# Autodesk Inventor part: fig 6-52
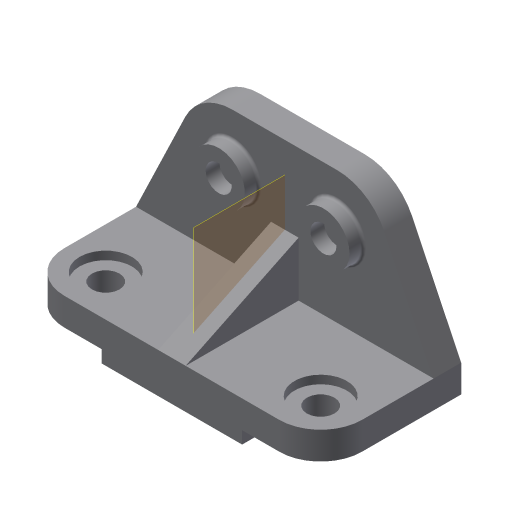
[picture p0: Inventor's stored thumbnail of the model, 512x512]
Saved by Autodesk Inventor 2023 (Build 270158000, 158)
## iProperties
Created: 2001-12
Part Number: fig 6-52
Document SubType Name: Modeling
Designer: Renu Muthoo
Density: 1 g/cm^3
Material: Generic
Appearance: Default
Control State: 0
Master: False
Checked Out: False
Shininess: 77.0
Length Units: 11269
Angle Units: 11279
Time Units: 11290
Mass Units: 11283
Length Display Precision: 3
Angle Display Precision: 2
Density: 0.0
Volumn: 0.0
Area: 0.0
PropertySet Name: Model Information
Author: Renu Muthoo
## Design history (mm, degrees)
node "Sketch1"
sketch "Sketch2"
  geometry: L1 (-67.219, 19.116)-(148.781, 19.116); L2 (148.781, 19.116)-(148.781, -0.884); L3 (-67.219, -0.884)-(-67.219, 19.116); L4 (-10.219, -0.884)-(-10.219, -9.884); L5 (-10.219, -9.884)-(91.781, -9.884); L6 (91.781, -9.884)-(91.781, -0.884); L7 (148.781, -0.884)-(91.781, -0.884); L8 (-10.219, -0.884)-(-67.219, -0.884)
  constraints: 16 end point, 5 parallel, 4 perpendicular, 2 equal length, 1 horizontal
  dimensions: "d0" = 102 distance of L4.end L5.end; "d1" = 57 distance of L4.start L3.start; "d2" = 29 distance between parallel lines of L1 L5; "d3" = 20 distance of L1.end L2.end
extrude "Extrusion1" new body sketch "Sketch2" distance "d4" = 102; taper "d5" = 0 deg
sketch "Sketch3"
  geometry: L1 (67.219, -19.116)-(-148.781, -19.116) reference; L2 (67.219, -19.116)-(31.475, -93.564); L3 (-2.781, -115.116)-(-78.781, -115.116); L4 (-113.038, -93.564)-(-148.781, -19.116); A1 r 38 centre (-2.781, -77.116) between (-2.781, -115.116) and (31.475, -93.564); A2 r 38 centre (-78.781, -77.116) between (-113.038, -93.564) and (-78.781, -115.116)
  constraints: 6 end point, 4 point on circle, 4 tangent, 2 centre point, 1 equal length, 1 equal radius, 1 parallel
  dimensions: "d6" = 96 distance between parallel lines of L3 L1; "d7" = 38 radius of A1; "d8" = 76 distance of A2.centre A1.centre
extrude "Extrusion2" join sketch "Sketch3" distance "d9" = 20; taper "d10" = 0 deg
fillet "Fillet1" dims "d11" = 30
workplane "Work Plane1"
sketch "Sketch5"
  geometry: A1 r 30 centre (-30, 0) between (-30, -30) and (0, 0) reference; 1 further point
  constraints: 1 coincident
hole "Hole1" sketch "Sketch5" at (-30, 0) diameter "d16" = 20; stored, may be unused: countersink angle "d20" = 82 deg, drill point angle "d22" = 118 deg; dims "d17" = 6, "d18" = 38, "d19" = 6, "d21" = 8
sketch "Sketch6"
  geometry: C1 r 19 at (-2.781, 77.116); C2 r 9.5 at (-2.781, 77.116); A1 r 38 centre (-2.781, 77.116) between (31.475, 93.564) and (-2.781, 115.116) reference
  constraints: 2 centre point, 2 coincident
  dimensions: "d23" = 38 diameter of C1; "d24" = 19 diameter of C2
extrude "Extrusion3" join sketch "Sketch6" distance "d25" = 10; taper "d26" = 0 deg
sketch "Sketch7"
  geometry: L1 (0, -82)-(-39.557, 0); L2 (0, -82)-(20, -82) reference; L3 (29, 22.405)-(29, -82); L4 (29, -82)-(0, -82); L5 (0, -82)-(0, 0); L6 (0, 0)-(-90.034, 0); L7 (-90.034, 0)-(-90.034, 22.405); L8 (-90.034, 22.405)-(29, 22.405); L9 (0, 0)-(-74.447, 0) reference
  constraints: 14 end point, 1 collinear, 1 point on line
feature "Rib3" sketch "Sketch7" dims "d35" = 10, "d36" = 20
fillet "Fillet3" dims "d37" = 2
mirror "Mirror4"
body "Solid1"
other parameters: "d12" = -108
